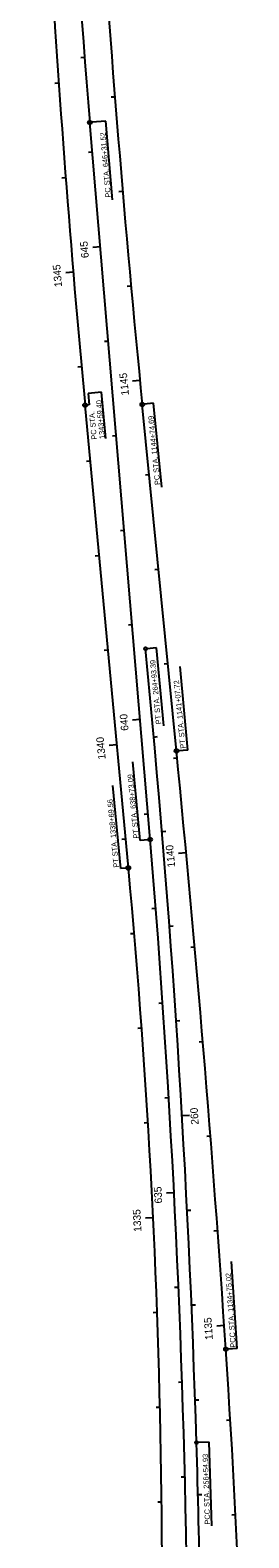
# Model space of a CAD drawing. Extents: x 919451 to 931682, y 583214 to 665619.
# Drawn here: x 928940 to 929170, y 638981 to 640570 of the extents above; entities that cross this region are included whole.
import ezdxf

# ---------------------------------------------------------------- set-up
doc = ezdxf.new("R2010")
doc.units = 0
for name, color, linetype in [('CLConst_dp', 7, 'Continuous'), ('ScratchEle_dp', 7, 'Continuous'), ('StationTicL_dp', 7, 'Continuous'), ('StationTicS_dp', 7, 'Continuous'), ('TextBLStation', 7, 'Continuous')]:
    doc.layers.add(name, color=color, linetype=linetype)

msp = doc.modelspace()

# ---------------------------------------------------------------- linework, layer by layer
at = {"layer": 'CLConst_dp'}
for p, q in [((929066.1, 639717.3), (929002.6, 640473)), ((929043.1, 639687.3), (928997.5, 640175)), ((929093.8, 639810.6), (929057.8, 640175.8))]:
    msp.add_line(p, q, dxfattribs=at)
for centre, radius, start, end in [((943200.7, 641503.4), 14265.2, 181.38944, 185.34316), ((940421.6, 641432.2), 11459.2, 181.38944, 184.80152), ((946164.4, 641863), 17189.6, 183.76149, 185.63271), ((916811.5, 638710.1), 12309, 1.72985, 5.63272), ((909344, 637862.7), 19845.6, 3.80604, 5.63271), ((917647.1, 638758.1), 11459.2, 0.62242, 4.80152), ((920885.8, 638924.4), 8192.9, 355.79449, 5.34316), ((918208, 638452.4), 10962, 356.74679, 3.80604), ((917055.6, 638717.5), 12064.8, 0.94631, 1.72985)]:
    msp.add_arc(centre, radius, start, end, dxfattribs=at)
at = {"layer": 'StationTicL_dp'}
for p, q in [((929019.5, 640474.4), (929004.6, 640473.2)), ((929026.5, 640391.5), (929019.5, 640474.4)), ((929014.9, 640188.7), (929000.9, 640187.4)), ((929000.9, 640187.4), (929002, 640175.4)), ((929019.5, 640139.8), (929014.9, 640188.7)), ((929002, 640175.4), (928999.5, 640175.2)), ((929069.7, 640177), (929059.8, 640176)), ((929078.5, 640088.7), (929069.7, 640177)), ((929072.6, 639919.2), (929062.7, 639918.3)), ((929080.4, 639837.2), (929072.6, 639919.2)), ((929105.8, 639811.5), (929097.6, 639899.5)), ((929105.8, 639811.5), (929095.8, 639810.6)), ((929055.5, 639716.1), (929047.8, 639799.1)), ((929035.1, 639686.6), (929026.9, 639774.3)), ((929064.1, 639717), (929055.5, 639716.1)), ((929041.1, 639687.1), (929035.1, 639686.6)), ((929157.9, 639180.7), (929151.7, 639272.7)), ((929157.9, 639180.7), (929147.9, 639180.1)), ((929128.2, 639082.1), (929116.5, 639081.7)), ((929131, 638993.9), (929128.2, 639082.1))]:
    msp.add_line(p, q, dxfattribs=at)
for centre, radius in [((929002.6, 640473), 2), ((928997.5, 640175), 2), ((929057.8, 640175.8), 2), ((929061.1, 639918.3), 1.6), ((929093.8, 639810.6), 2), ((929066.1, 639717.3), 2), ((929043.1, 639687.3), 2), ((929145.9, 639180.1), 2), ((929114.9, 639081.7), 1.6)]:
    msp.add_circle(centre, radius, dxfattribs=at)
at = {"layer": 'StationTicS_dp'}
for p, q in [((929013.6, 640342), (929005.6, 640341.3)), ((928985.1, 640315.1), (928977.1, 640314.4)), ((929055.3, 640201), (929047.4, 640200.2)), ((929055.5, 639843.7), (929047.5, 639843.1)), ((929030.9, 639817.2), (929023, 639816.4)), ((929104.1, 639703.4), (929096.1, 639702.6)), ((929099.7, 639426.4), (929107.7, 639426.9)), ((929091.3, 639345), (929083.3, 639344.6)), ((929069.2, 639318.7), (929061.2, 639318.3)), ((929144.2, 639205), (929136.2, 639204.5))]:
    msp.add_line(p, q, dxfattribs=at)
at = {"layer": 'TextBLStation'}
for p, q in [((928997.1, 640541.3), (928993.1, 640541)), ((928969.8, 640514.5), (928965.8, 640514.2)), ((929028.9, 640499.8), (929024.9, 640499.5)), ((929005.2, 640441.6), (929001.3, 640441.3)), ((928977.1, 640414.7), (928973.1, 640414.4)), ((929037.2, 640400.2), (929033.2, 640399.8)), ((929046, 640300.6), (929042, 640300.2)), ((929022, 640242.3), (929018, 640242)), ((928993.7, 640215.4), (928989.8, 640215.1)), ((929030.4, 640142.7), (929026.4, 640142.3)), ((929003, 640115.9), (928999, 640115.5)), ((929065.1, 640101.5), (929061.2, 640101.1)), ((929038.7, 640043), (929034.7, 640042.7)), ((929012.3, 640016.3), (929008.3, 640015.9)), ((929074.9, 640002), (929071, 640001.6)), ((929047.1, 639943.4), (929043.1, 639943)), ((929021.6, 639916.7), (929017.6, 639916.4)), ((929084.8, 639902.4), (929080.8, 639902.1)), ((929069.9, 639825.3), (929073.9, 639825.7)), ((929094.6, 639802.9), (929090.6, 639802.5)), ((929063.8, 639744.1), (929059.8, 639743.7)), ((929078.6, 639725.7), (929082.5, 639726)), ((929040.2, 639717.6), (929036.3, 639717.2)), ((929072, 639644.4), (929068, 639644.1)), ((929049.3, 639618), (929045.3, 639617.7)), ((929086.4, 639626), (929090.4, 639626.3)), ((929113.1, 639603.8), (929109.1, 639603.4)), ((929079.3, 639544.7), (929075.3, 639544.4)), ((929057.1, 639518.3), (929053.1, 639518)), ((929093.4, 639526.2), (929097.4, 639526.5)), ((929121.6, 639504.2), (929117.7, 639503.8)), ((929085.7, 639444.9), (929081.7, 639444.6)), ((929063.8, 639418.6), (929059.8, 639418.3)), ((929129.7, 639404.5), (929125.7, 639404.2)), ((929105.1, 639326.6), (929109.1, 639326.8)), ((929137.2, 639304.8), (929133.2, 639304.5)), ((929095.9, 639245.1), (929091.9, 639245)), ((929073.4, 639218.8), (929069.4, 639218.6)), ((929109.7, 639226.7), (929113.7, 639226.9)), ((929099.8, 639145.2), (929095.8, 639145.1)), ((929113.5, 639126.8), (929117.5, 639126.9)), ((929076.4, 639118.8), (929072.4, 639118.7)), ((929150.6, 639105.2), (929146.6, 639105)), ((929102.7, 639045.3), (929098.7, 639045.2)), ((929116.4, 639026.8), (929120.4, 639026.9)), ((929078.1, 639018.8), (929074.1, 639018.8)), ((929156.1, 639005.4), (929152.1, 639005.2))]:
    msp.add_line(p, q, dxfattribs=at)

# ---------------------------------------------------------------- texts
at = {"layer": 'ScratchEle_dp'}
for s, rotation, p in [('645', 94.8015, (929001.5, 640330.4)), ('1345', 94.7784, (928973.3, 640299.9)), ('1145', 95.5483, (929043.8, 640185.7)), ('640', 94.8015, (929043.4, 639832.2)), ('1340', 95.3432, (929019.3, 639802)), ('1140', 95.3217, (929092.5, 639688.2)), ('260', 93.3361, (929117.2, 639417)), ('635', 92.936, (929078.8, 639333.9)), ('1335', 92.7587, (929056.9, 639304)), ('1135', 93.8782, (929132.2, 639190.1))]:
    msp.add_text(s, height=8, rotation=rotation, dxfattribs=at).set_placement(p)
at = {"layer": 'StationTicL_dp'}
for s, rotation, p in [('PC STA. 646+31.52', 94.8015, (929024.7, 640394.1)), ('1343+59.40', 95.3432, (929018.4, 640139.7)), ('PC STA.', 95.3432, (929010, 640139)), ('PC STA. 1144+74.69', 95.6327, (929076.7, 640091.2)), ('PT STA. 264+93.39', 95.4154, (929077.8, 639839)), ('PT STA. 1141+07.72', 95.6327, (929103.5, 639813.3)), ('PT STA. 638+73.09', 95.4926, (929054.2, 639718.6)), ('PT STA. 1338+69.56', 95.3432, (929033.2, 639687.9)), ('PCC STA. 1134+75.02', 93.806, (929156.3, 639181.9)), ('PCC STA. 256+54.93', 91.8348, (929129.3, 638995.4))]:
    msp.add_text(s, height=5.6, rotation=rotation, dxfattribs=at).set_placement(p)

doc.saveas('drawing.dxf')
